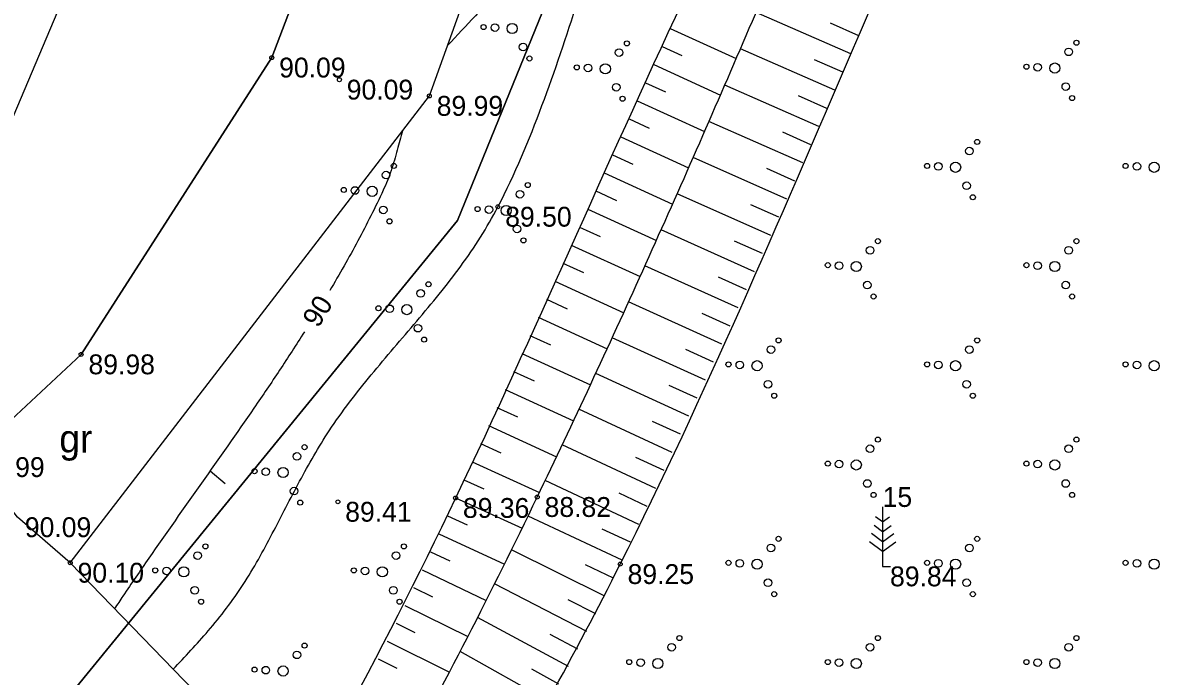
# Model space of a CAD drawing. Extents: x 635228 to 635525, y 248590 to 248800.
# Drawn here: x 635326.51 to 635355.15, y 248677.18 to 248693.64 of the extents above; entities that cross this region are included whole.
import ezdxf

# ---------------------------------------------------------------- set-up
doc = ezdxf.new("R2010")
doc.units = 0
for name, color, linetype in [('CELI_CMAL_####_####_#', 7, 'Continuous'), ('CELI_CSEG_####_TKST_#', 7, 'Continuous'), ('RAMI_UZMR_####_####_#', 7, 'Continuous'), ('RELJ_AATZ_####_TKST_#', 7, 'Continuous'), ('RELJ_ELEM_####_####_#', 7, 'Continuous'), ('RELJ_HORZ_####_TKST_#', 7, 'Continuous'), ('RELJ_HORZ_PAMT_####_#', 7, 'Continuous'), ('RELJ_HORZ_RESN_####_#', 7, 'Continuous'), ('RELJ_NOGA_####_####_#', 7, 'Continuous'), ('RELJ_NOGL_####_####_#', 7, 'Continuous'), ('ROBZ_PROJ_####_####_#', 7, 'Continuous'), ('ROBZ_UZMR_####_####_#', 7, 'Continuous'), ('TERT_DIAM_####_TKST_#', 7, 'Continuous'), ('TERT_ELEM_####_####_#', 7, 'Continuous'), ('TERT_KONT_####_####_#', 7, 'Continuous')]:
    doc.layers.add(name, color=color, linetype=linetype)

msp = doc.modelspace()

# ---------------------------------------------------------------- linework, layer by layer
at = {"layer": 'CELI_CMAL_####_####_#'}
for points in [[(635327.703, 248680.035), (635336.747, 248691.797), (635341.71, 248705.602), (635344.776, 248717.251), (635350.856, 248738.106), (635354.904, 248753.168), (635356.755, 248761.086), (635356.988, 248762.081)], [(635352.126, 248761.775), (635351.394, 248755.812), (635346.791, 248738.298), (635340.529, 248716.56), (635338.144, 248706.864), (635332.779, 248692.762), (635327.977, 248685.285), (635325.201, 248682.696)]]:
    msp.add_lwpolyline(points, dxfattribs=at)
at = {"layer": 'RAMI_UZMR_####_####_#'}
msp.add_lwpolyline([(635379.918, 248627.738), (635364.657, 248634.365), (635359.326, 248636.387), (635355.893, 248639.014), (635323.971, 248655.917), (635326.8, 248663.851), (635331.354, 248676.262), (635327.703, 248680.035), (635326.374, 248681.182), (635325.201, 248682.696), (635327.977, 248685.285), (635332.779, 248692.762), (635338.144, 248706.864), (635340.529, 248716.56), (635346.791, 248738.298), (635351.394, 248755.812), (635352.126, 248761.775)], dxfattribs=at)
at = {"layer": 'RELJ_ELEM_####_####_#'}
for centre in [(635332.779, 248692.762), (635334.481, 248692.206), (635336.747, 248691.797), (635338.472, 248689.004), (635327.977, 248685.285), (635334.443, 248681.571), (635337.407, 248681.667), (635339.464, 248681.691), (635327.703, 248680.035), (635341.554, 248680.001)]:
    msp.add_circle(centre, 0.05, dxfattribs=at)
at = {"layer": 'RELJ_HORZ_PAMT_####_#'}
msp.add_spline([(635330.297, 248677.354), (635331.177, 248678.319), (635332.06, 248679.489), (635332.793, 248680.772), (635333.481, 248682.089), (635334.226, 248683.36), (635335.284, 248684.77), (635336.431, 248686.125), (635337.538, 248687.508), (635338.035, 248688.237), (635338.472, 248689.004), (635339.583, 248691.554), (635340.487, 248694.188), (635341.335, 248696.84), (635341.787, 248698.153), (635342.281, 248699.447), (635343.206, 248701.423), (635344.222, 248703.369), (635345.157, 248705.345), (635345.54, 248706.364), (635345.837, 248707.412), (635346.445, 248710.352), (635346.944, 248713.307), (635347.835, 248719.233), (635348.116, 248721.113), (635348.378, 248722.995), (635348.645, 248724.878), (635348.937, 248726.758), (635349.503, 248728.159), (635350.332, 248729.539), (635351.235, 248730.852), (635351.672, 248731.412), (635352.153, 248731.934), (635352.67, 248732.415), (635353.216, 248732.849), (635353.585, 248732.808), (635353.973, 248732.393), (635354.375, 248731.871), (635354.581, 248731.654), (635354.79, 248731.511), (635355.514, 248731.162), (635356.357, 248730.815), (635357.156, 248730.69), (635357.748, 248731.008), (635358.207, 248731.666), (635358.657, 248732.33), (635359.531, 248733.675), (635361.193, 248736.42), (635362.771, 248739.216), (635364.301, 248742.038), (635372.089, 248756.526)], degree=3, dxfattribs=at)
at = {"layer": 'RELJ_HORZ_RESN_####_#'}
msp.add_line((635331.227, 248682.355), (635331.606, 248682.029), dxfattribs=at)
for points in [[(635346.739, 248717.915), (635346.608, 248716.083), (635346.466, 248714.252), (635346.348, 248713.214), (635346.269, 248712.697), (635346.182, 248712.182), (635345.98, 248711.16), (635345.727, 248710.151), (635345.266, 248708.625), (635344.77, 248707.113), (635344.229, 248705.619), (635343.634, 248704.146), (635343.044, 248702.77), (635342.451, 248701.393), (635341.838, 248700.031), (635341.518, 248699.356), (635341.19, 248698.685), (635340.494, 248697.382), (635339.719, 248696.124), (635339.299, 248695.519), (635338.859, 248694.931), (635337.907, 248693.816), (635337.205, 248693.072)], [(635342.967, 248665.189), (635350.649, 248671.097), (635353.044, 248672.199), (635354.147, 248672.641), (635355.27, 248673.022), (635357.544, 248673.711), (635360.916, 248674.993), (635361.461, 248675.281), (635362, 248675.6), (635362.585, 248676.091), (635362.941, 248676.666), (635363.082, 248678.034), (635362.825, 248678.873), (635362.542, 248679.71), (635361.896, 248681.359), (635361.504, 248682.258), (635361.094, 248683.142), (635360.687, 248684.033), (635360.306, 248684.949), (635359.942, 248686.647), (635360.049, 248687.813), (635360.176, 248688.176), (635361.529, 248691.159), (635363.072, 248694.104), (635364.881, 248696.95), (635367.032, 248699.635), (635368.378, 248700.848), (635369.286, 248701.486)], [(635336.071, 248690.918), (635335.941, 248690.434), (635335.784, 248689.918), (635335.692, 248689.666), (635335.586, 248689.42), (635335.274, 248688.777), (635334.945, 248688.143), (635334.6, 248687.515), (635334.241, 248686.894)], [(635333.601, 248685.852), (635332.976, 248684.889), (635332.331, 248683.934), (635331.007, 248682.041), (635329.681, 248680.149), (635329.031, 248679.197), (635328.82, 248678.88)]]:
    msp.add_spline(points, degree=3, dxfattribs=at)
at = {"layer": 'RELJ_NOGA_####_####_#'}
for p, q in [((635347.363, 248692.856), (635344.976, 248693.899)), ((635342.815, 248693.495), (635344.475, 248692.737)), ((635347.563, 248693.314), (635346.846, 248693.628)), ((635342.608, 248693.041), (635343.108, 248692.812)), ((635346.962, 248691.94), (635344.582, 248692.983)), ((635342.4, 248692.586), (635344.078, 248691.819)), ((635347.162, 248692.398), (635346.448, 248692.711)), ((635342.192, 248692.131), (635342.698, 248691.9)), ((635346.559, 248691.025), (635344.186, 248692.068)), ((635341.984, 248691.677), (635343.678, 248690.902)), ((635346.761, 248691.482), (635346.048, 248691.796)), ((635341.776, 248691.222), (635342.286, 248690.988)), ((635346.156, 248690.11), (635343.789, 248691.156)), ((635346.358, 248690.567), (635345.647, 248690.881)), ((635341.568, 248690.767), (635343.276, 248689.986)), ((635341.36, 248690.312), (635341.874, 248690.077)), ((635345.751, 248689.195), (635343.39, 248690.245)), ((635345.953, 248689.653), (635345.244, 248689.967)), ((635341.152, 248689.858), (635342.871, 248689.072)), ((635340.944, 248689.403), (635341.461, 248689.166)), ((635345.344, 248688.282), (635342.987, 248689.332)), ((635340.736, 248688.948), (635342.464, 248688.158)), ((635345.548, 248688.739), (635344.84, 248689.054)), ((635340.529, 248688.493), (635341.048, 248688.256)), ((635344.936, 248687.369), (635342.583, 248688.424)), ((635340.321, 248688.039), (635342.054, 248687.246)), ((635345.14, 248687.825), (635344.434, 248688.141)), ((635340.113, 248687.584), (635340.633, 248687.346)), ((635344.526, 248686.457), (635342.175, 248687.515)), ((635339.905, 248687.129), (635341.641, 248686.336)), ((635344.731, 248686.913), (635344.026, 248687.23)), ((635339.697, 248686.675), (635340.218, 248686.436)), ((635344.114, 248685.546), (635341.766, 248686.61)), ((635339.489, 248686.22), (635341.224, 248685.426)), ((635344.32, 248686.001), (635343.615, 248686.32)), ((635339.281, 248685.765), (635339.801, 248685.527)), ((635343.7, 248684.635), (635341.352, 248685.704)), ((635343.907, 248685.09), (635343.203, 248685.411)), ((635339.073, 248685.31), (635340.804, 248684.519)), ((635338.865, 248684.856), (635339.383, 248684.619)), ((635343.284, 248683.726), (635340.936, 248684.804)), ((635343.492, 248684.181), (635342.788, 248684.503)), ((635338.657, 248684.401), (635340.38, 248683.613)), ((635338.449, 248683.946), (635338.964, 248683.711)), ((635342.866, 248682.817), (635340.516, 248683.903)), ((635338.241, 248683.492), (635339.952, 248682.709)), ((635343.076, 248683.272), (635342.371, 248683.595)), ((635338.033, 248683.037), (635338.544, 248682.803)), ((635342.447, 248681.91), (635340.092, 248683.004)), ((635337.825, 248682.582), (635339.52, 248681.807)), ((635342.657, 248682.363), (635341.951, 248682.689)), ((635337.618, 248682.127), (635338.123, 248681.896)), ((635342.024, 248681.003), (635339.664, 248682.107)), ((635337.41, 248681.673), (635339.083, 248680.907)), ((635342.236, 248681.456), (635341.528, 248681.786)), ((635337.201, 248681.218), (635337.698, 248680.988)), ((635341.6, 248680.098), (635339.232, 248681.211)), ((635336.99, 248680.765), (635338.636, 248679.997)), ((635341.812, 248680.551), (635341.103, 248680.883)), ((635336.778, 248680.312), (635337.267, 248680.082)), ((635341.166, 248679.197), (635338.814, 248680.358)), ((635341.385, 248679.646), (635340.676, 248679.986)), ((635336.563, 248679.861), (635338.181, 248679.087)), ((635336.347, 248679.41), (635336.829, 248679.178)), ((635340.715, 248678.304), (635338.391, 248679.506)), ((635340.943, 248678.75), (635340.241, 248679.105)), ((635336.129, 248678.96), (635337.72, 248678.18)), ((635335.908, 248678.511), (635336.382, 248678.277)), ((635340.248, 248677.42), (635337.961, 248678.653)), ((635340.483, 248677.861), (635339.791, 248678.227)), ((635335.685, 248678.064), (635337.253, 248677.277)), ((635335.46, 248677.618), (635335.926, 248677.38)), ((635339.766, 248676.544), (635337.526, 248677.802)), ((635340.009, 248676.981), (635339.33, 248677.356))]:
    msp.add_line(p, q, dxfattribs=at)
for points in [[(635375.27, 248754.857), (635369.314, 248744.971), (635367.429, 248741.507), (635365.696, 248737.957), (635363.943, 248734.417), (635363.006, 248732.681), (635362, 248730.984), (635361.355, 248730.103), (635360.628, 248729.283), (635359.885, 248728.474), (635359.193, 248727.625), (635357.58, 248725.368), (635356.018, 248723.079), (635353.089, 248718.349), (635349.569, 248710.638), (635349.163, 248709.221), (635348.864, 248707.772), (635348.539, 248706.335), (635348.053, 248704.954), (635343.12, 248694.162), (635337.407, 248681.667), (635331.093, 248670.147), (635326.8, 248663.851)], [(635326.8, 248663.851), (635325.31, 248661.345), (635325.174, 248660.918), (635325.219, 248660.451), (635325.416, 248659.984), (635325.736, 248659.553), (635326.126, 248659.27), (635326.575, 248659.146), (635327.409, 248659.333), (635327.907, 248659.688), (635328.397, 248660.078), (635328.864, 248660.506), (635329.288, 248660.978), (635331.594, 248663.918), (635332.687, 248665.412), (635333.734, 248666.95), (635337.875, 248673.353), (635341.554, 248680.001), (635347.428, 248693.006), (635353.063, 248706.101), (635354.098, 248708.621), (635355.097, 248711.155), (635356.117, 248713.682), (635356.653, 248714.935), (635357.216, 248716.179), (635358.916, 248719.218), (635360.822, 248722.14), (635362.339, 248724.363), (635363.916, 248726.545), (635365.467, 248728.744), (635366.906, 248731.015), (635368.464, 248733.981), (635369.863, 248737.03), (635371.249, 248740.086), (635372.769, 248743.072), (635378.435, 248753.196)]]:
    msp.add_spline(points, degree=3, dxfattribs=at)
at = {"layer": 'RELJ_NOGL_####_####_#'}
msp.add_spline([(635326.936, 248660.713), (635331.766, 248667.928), (635333.88, 248671.254), (635335.853, 248674.668), (635337.706, 248678.153), (635339.464, 248681.691), (635342.12, 248687.391), (635344.65, 248693.14), (635347.108, 248698.916), (635349.548, 248704.698), (635350.777, 248707.84), (635351.91, 248711.022), (635353.067, 248714.195), (635353.692, 248715.764), (635354.368, 248717.312), (635355.034, 248718.536), (635355.835, 248719.677), (635357.677, 248721.811), (635359.567, 248723.919), (635361.176, 248726.206), (635362.355, 248728.434), (635362.939, 248729.551), (635363.546, 248730.656), (635367.422, 248737.348), (635371.307, 248744.035), (635372.506, 248746.487), (635373.579, 248749.023), (635374.785, 248751.459), (635376.384, 248753.612), (635376.807, 248754.05)], degree=3, dxfattribs=at)
at = {"layer": 'ROBZ_PROJ_####_####_#'}
msp.add_lwpolyline([(635363.321, 248797.676), (635360.888, 248769.918), (635360.483, 248762.615), (635343.343, 248703.12), (635337.46, 248688.66), (635327.79, 248676.828), (635329.653, 248676.366), (635325.542, 248659.74), (635315.4, 248665.602), (635272.581, 248690.35), (635264.056, 248694.511), (635270.042, 248696.015), (635282.096, 248694.845), (635298.597, 248686.068), (635311.236, 248680.45), (635322.498, 248682.379), (635341.086, 248726.313), (635346.481, 248751.583), (635353.471, 248778.803), (635354.805, 248797.676)], dxfattribs=at)
at = {"layer": 'ROBZ_UZMR_####_####_#'}
msp.add_lwpolyline([(635325.542, 248659.74), (635329.653, 248676.366), (635327.79, 248676.828), (635337.46, 248688.66), (635343.343, 248703.12), (635360.483, 248762.615), (635458.607, 248711.134), (635465.459, 248707.539), (635439.457, 248681.038), (635424.543, 248670.014), (635420.979, 248667.379), (635407.07, 248653.18), (635400.067, 248641.149), (635395.162, 248617.539), (635389.031, 248621.062), (635375.858, 248629.115)], close=True, dxfattribs=at)
at = {"layer": 'TERT_ELEM_####_####_#'}
for p, q in [((635348.163, 248681.443), (635348.163, 248679.943)), ((635348.163, 248681.067), (635347.987, 248681.195)), ((635348.163, 248681.067), (635348.337, 248681.195)), ((635348.163, 248680.567), (635347.885, 248680.771)), ((635348.163, 248680.817), (635347.947, 248680.975)), ((635348.163, 248680.817), (635348.379, 248680.975)), ((635348.163, 248680.567), (635348.441, 248680.771)), ((635348.163, 248680.317), (635347.831, 248680.561)), ((635348.163, 248680.317), (635348.497, 248680.561)), ((635348.163, 248679.943), (635348.363, 248679.943))]:
    msp.add_line(p, q, dxfattribs=at)
for centre, radius in [((635338.114, 248693.531), 0.064), ((635338.398, 248693.518), 0.096), ((635338.832, 248693.497), 0.128), ((635339.108, 248693.03), 0.096), ((635341.723, 248693.122), 0.064), ((635353.044, 248693.139), 0.064), ((635339.266, 248692.741), 0.064), ((635341.526, 248692.89), 0.096), ((635352.848, 248692.908), 0.096), ((635340.46, 248692.517), 0.064), ((635340.745, 248692.503), 0.096), ((635341.179, 248692.482), 0.128), ((635351.782, 248692.534), 0.064), ((635352.066, 248692.521), 0.096), ((635352.5, 248692.5), 0.128), ((635341.455, 248692.015), 0.096), ((635352.776, 248692.033), 0.096), ((635341.613, 248691.726), 0.064), ((635352.934, 248691.744), 0.064), ((635350.348, 248690.408), 0.096), ((635350.544, 248690.639), 0.064), ((635335.853, 248690.034), 0.064), ((635349.282, 248690.034), 0.064), ((635349.566, 248690.021), 0.096), ((635350, 248690), 0.128), ((635354.282, 248690.034), 0.064), ((635354.566, 248690.021), 0.096), ((635355, 248690), 0.128), ((635335.657, 248689.802), 0.096), ((635334.591, 248689.429), 0.064), ((635334.875, 248689.415), 0.096), ((635335.309, 248689.394), 0.128), ((635339.029, 248689.321), 0.096), ((635339.226, 248689.552), 0.064), ((635350.276, 248689.533), 0.096), ((635350.434, 248689.244), 0.064), ((635335.586, 248688.927), 0.096), ((635337.963, 248688.947), 0.064), ((635338.248, 248688.934), 0.096), ((635338.682, 248688.913), 0.128), ((635335.743, 248688.638), 0.064), ((635338.958, 248688.446), 0.096), ((635339.115, 248688.157), 0.064), ((635348.044, 248688.139), 0.064), ((635353.044, 248688.139), 0.064), ((635347.848, 248687.908), 0.096), ((635352.848, 248687.908), 0.096), ((635347.5, 248687.5), 0.128), ((635352.5, 248687.5), 0.128), ((635346.782, 248687.534), 0.064), ((635347.066, 248687.521), 0.096), ((635351.782, 248687.534), 0.064), ((635352.066, 248687.521), 0.096), ((635336.726, 248687.052), 0.064), ((635347.776, 248687.033), 0.096), ((635352.776, 248687.033), 0.096), ((635336.529, 248686.821), 0.096), ((635347.934, 248686.744), 0.064), ((635352.934, 248686.744), 0.064), ((635335.463, 248686.447), 0.064), ((635335.748, 248686.434), 0.096), ((635336.182, 248686.413), 0.128), ((635336.458, 248685.946), 0.096), ((635336.615, 248685.657), 0.064), ((635345.544, 248685.639), 0.064), ((635350.544, 248685.639), 0.064), ((635345.348, 248685.408), 0.096), ((635350.348, 248685.408), 0.096), ((635344.282, 248685.034), 0.064), ((635344.566, 248685.021), 0.096), ((635345, 248685), 0.128), ((635349.282, 248685.034), 0.064), ((635349.566, 248685.021), 0.096), ((635350, 248685), 0.128), ((635354.282, 248685.034), 0.064), ((635354.566, 248685.021), 0.096), ((635355, 248685), 0.128), ((635345.276, 248684.533), 0.096), ((635350.276, 248684.533), 0.096), ((635345.434, 248684.244), 0.064), ((635350.434, 248684.244), 0.064), ((635348.044, 248683.139), 0.064), ((635353.044, 248683.139), 0.064), ((635333.411, 248682.716), 0.096), ((635333.607, 248682.948), 0.064), ((635347.848, 248682.908), 0.096), ((635352.848, 248682.908), 0.096), ((635346.782, 248682.534), 0.064), ((635347.066, 248682.521), 0.096), ((635347.5, 248682.5), 0.128), ((635351.782, 248682.534), 0.064), ((635352.066, 248682.521), 0.096), ((635352.5, 248682.5), 0.128), ((635332.345, 248682.343), 0.064), ((635332.629, 248682.33), 0.096), ((635333.063, 248682.309), 0.128), ((635333.34, 248681.842), 0.096), ((635347.776, 248682.033), 0.096), ((635352.776, 248682.033), 0.096), ((635333.497, 248681.553), 0.064), ((635347.934, 248681.744), 0.064), ((635352.934, 248681.744), 0.064), ((635331.107, 248680.448), 0.064), ((635336.107, 248680.448), 0.064), ((635345.348, 248680.408), 0.096), ((635345.544, 248680.639), 0.064), ((635350.348, 248680.408), 0.096), ((635350.544, 248680.639), 0.064), ((635330.911, 248680.216), 0.096), ((635335.911, 248680.216), 0.096), ((635329.845, 248679.843), 0.064), ((635330.129, 248679.83), 0.096), ((635330.563, 248679.809), 0.128), ((635334.845, 248679.843), 0.064), ((635335.129, 248679.83), 0.096), ((635335.563, 248679.809), 0.128), ((635344.282, 248680.034), 0.064), ((635344.566, 248680.021), 0.096), ((635345, 248680), 0.128), ((635349.282, 248680.034), 0.064), ((635349.566, 248680.021), 0.096), ((635350, 248680), 0.128), ((635354.282, 248680.034), 0.064), ((635354.566, 248680.021), 0.096), ((635355, 248680), 0.128), ((635345.276, 248679.533), 0.096), ((635350.276, 248679.533), 0.096), ((635330.84, 248679.342), 0.096), ((635335.84, 248679.342), 0.096), ((635330.997, 248679.053), 0.064), ((635335.997, 248679.053), 0.064), ((635345.434, 248679.244), 0.064), ((635350.434, 248679.244), 0.064), ((635343.044, 248678.139), 0.064), ((635348.044, 248678.139), 0.064), ((635353.044, 248678.139), 0.064), ((635333.607, 248677.948), 0.064), ((635342.848, 248677.908), 0.096), ((635347.848, 248677.908), 0.096), ((635352.848, 248677.908), 0.096), ((635333.411, 248677.716), 0.096), ((635342.066, 248677.521), 0.096), ((635342.5, 248677.5), 0.128), ((635347.066, 248677.521), 0.096), ((635347.5, 248677.5), 0.128), ((635352.066, 248677.521), 0.096), ((635352.5, 248677.5), 0.128), ((635332.345, 248677.343), 0.064), ((635332.629, 248677.33), 0.096), ((635333.063, 248677.309), 0.128), ((635341.782, 248677.534), 0.064), ((635346.782, 248677.534), 0.064), ((635351.782, 248677.534), 0.064)]:
    msp.add_circle(centre, radius, dxfattribs=at)
at = {"layer": 'TERT_KONT_####_####_#'}
msp.add_spline([(635347.944, 248675.14), (635353.969, 248676.317), (635361.548, 248680.892), (635362.735, 248687.694), (635367.699, 248695.072), (635365.801, 248699.259), (635373.4, 248711.674), (635374.835, 248703.881), (635382.868, 248697.463), (635386.085, 248703.415)], degree=3, dxfattribs=at)

# ---------------------------------------------------------------- texts
at = {"layer": 'CELI_CSEG_####_TKST_#'}
msp.add_text('gr', height=0.7, dxfattribs=at).set_placement((635327.429, 248682.814))
at = {"layer": 'RELJ_AATZ_####_TKST_#'}
for s, p in [(' 90.09', (635332.779, 248692.262)), (' 90.09', (635334.481, 248691.706)), (' 89.99', (635336.747, 248691.297)), (' 89.50', (635338.472, 248688.504)), (' 89.98', (635327.977, 248684.785)), (' 89.99', (635325.201, 248682.196)), (' 89.36', (635337.407, 248681.167)), (' 88.82', (635339.464, 248681.191)), (' 89.41', (635334.443, 248681.071)), (' 90.09', (635326.374, 248680.682)), (' 90.10', (635327.703, 248679.535)), (' 89.25', (635341.554, 248679.501)), (' 89.84', (635348.163, 248679.443))]:
    msp.add_text(s, height=0.5, dxfattribs=at).set_placement(p)
at = {"layer": 'RELJ_HORZ_####_TKST_#'}
msp.add_text('90', height=0.5, rotation=58.4554, dxfattribs=at).set_placement((635333.949, 248685.932))
at = {"layer": 'TERT_DIAM_####_TKST_#'}
msp.add_text('15', height=0.5, dxfattribs=at).set_placement((635348.163, 248681.443))

doc.saveas('drawing.dxf')
